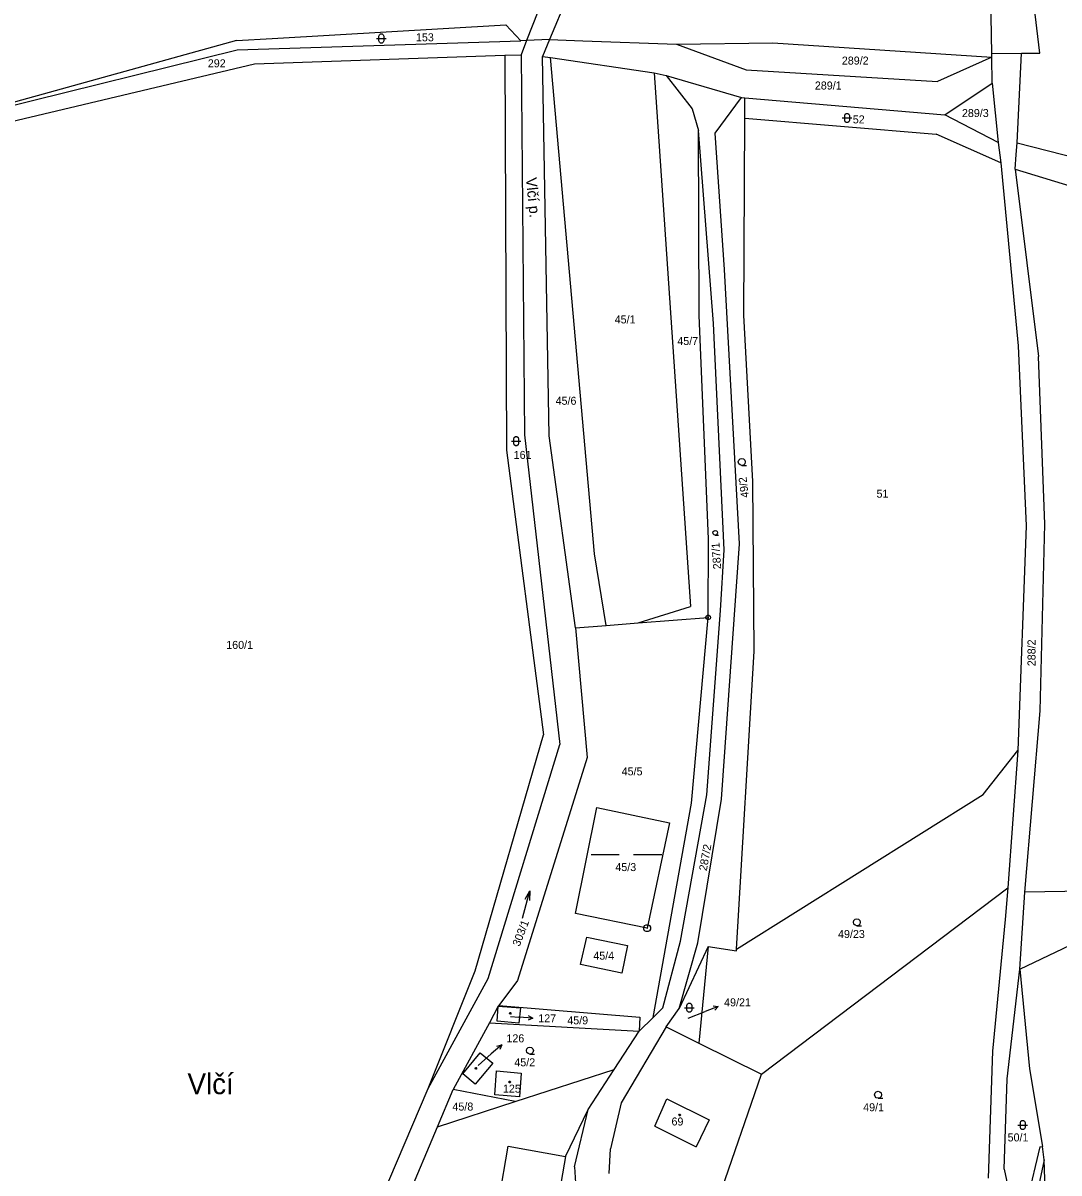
# Model space of a CAD drawing. Extents: x -780000 to -777378, y -1011169 to -1009297.
# Drawn here: x -779206.4 to -778986.4, y -1010124.6 to -1009880.5 of the extents above; entities that cross this region are included whole.
import ezdxf

# ---------------------------------------------------------------- set-up
doc = ezdxf.new("R2010")
doc.units = 0
for name, color, linetype in [('Default', 7, 'Continuous'), ('KN_HRANICE', 7, 'Continuous'), ('KN_KULTURY', 7, 'Continuous'), ('KN_PARCELY', 7, 'Continuous'), ('KN_SLUCKY', 7, 'Continuous')]:
    doc.layers.add(name, color=color, linetype=linetype)

# ---------------------------------------------------------------- blocks, each defined once
blk = doc.blocks.new('101')
at = {"layer": 'Default'}
blk.add_line((-0.05, 0), (0.05, 0), dxfattribs=at)
blk.add_lwpolyline([(0.19, 0.72), (0.53, 0.53), (0.72, 0.19), (0.72, -0.2), (0.53, -0.54), (0.19, -0.73), (-0.2, -0.73), (-0.54, -0.54), (-0.73, -0.2), (-0.73, 0.19), (-0.54, 0.53), (-0.2, 0.72), (0.19, 0.72)], dxfattribs=at)
blk = doc.blocks.new('304')
at = {"layer": 'Default'}
blk.add_lwpolyline([(0, 0), (-0.38, 0.1), (-0.65, 0.37), (-0.75, 0.74), (-0.65, 1.11), (-0.38, 1.38), (-0.01, 1.48), (0.36, 1.38), (0.63, 1.11), (0.73, 0.73), (0.63, 0.35), (0.36, 0.08), (-0.02, -0.02), (0.98, -0.02)], dxfattribs=at)
blk = doc.blocks.new('316')
at = {"layer": 'Default'}
for points in [[(-1, 1), (0.27, 1), (1, 1)], [(-0.5, 1.5), (-0.4, 1.79), (-0.15, 1.97), (0.16, 1.97), (0.41, 1.79), (0.51, 1.5), (0.51, 0.5), (0.41, 0.21), (0.16, 0.03), (-0.15, 0.03), (-0.4, 0.21), (-0.5, 0.5), (-0.5, 1.5)]]:
    blk.add_lwpolyline(points, dxfattribs=at)
blk = doc.blocks.new('802')
at = {"layer": 'Default'}
blk.add_line((-3, 0), (3, 0), dxfattribs=at)
blk.add_lwpolyline([(1, 0.5), (3, 0), (1, -0.5)], dxfattribs=at)
blk = doc.blocks.new('803')
at = {"layer": 'Default'}
for p, q in [((-7.5, 0), (-1.5, 0)), ((1.5, 0), (7.5, 0))]:
    blk.add_line(p, q, dxfattribs=at)
blk = doc.blocks.new('10292')
at = {"layer": 'Default'}
blk.add_line((0, 3), (0, 0), dxfattribs=at)
blk.add_lwpolyline([(-0.5, 2), (0, 3), (0.5, 2)], dxfattribs=at)
blk = doc.blocks.new('105')
at = {"layer": 'Default'}
blk.add_line((-0.12, 0), (0.12, 0), dxfattribs=at)
blk.add_lwpolyline([(0.15, 0.48), (0.4, 0.3), (0.5, 0.01), (0.4, -0.28), (0.15, -0.46), (-0.16, -0.46), (-0.41, -0.28), (-0.51, 0.01), (-0.41, 0.3), (-0.16, 0.48), (0.15, 0.48)], dxfattribs=at)
blk = doc.blocks.new('402')
at = {"layer": 'Default'}
blk.add_lwpolyline([(0.09, 0.15), (0.18, 0), (0.09, -0.15), (-0.09, -0.15), (-0.18, 0), (-0.09, 0.15), (0.09, 0.15)], dxfattribs=at)

msp = doc.modelspace()

# ---------------------------------------------------------------- linework, layer by layer
at = {"layer": 'KN_HRANICE'}
for p, q in [((-778990.51, -1009886.89), (-778995.32, -1009846.4)), ((-779090.96, -1009862.3), (-779099.45, -1009884.17)), ((-779085.09, -1009861.37), (-779094.6, -1009883.98)), ((-779000.69, -1009886.92), (-779001.1, -1009864.61)), ((-779153.46, -1009883.76), (-779103.85, -1009880.84)), ((-779100.65, -1009884.22), (-779103.85, -1009880.84)), ((-779161.05, -1009884.21), (-779228.01, -1009902.71)), ((-779161.05, -1009884.21), (-779153.46, -1009883.76)), ((-779160.94, -1009886.18), (-779100.65, -1009884.22)), ((-779099.45, -1009884.17), (-779100.65, -1009884.22)), ((-779099.45, -1009884.17), (-779100.62, -1009887.2)), ((-779094.6, -1009883.98), (-779099.45, -1009884.17)), ((-779094.6, -1009883.98), (-779096.11, -1009887.57)), ((-779094.6, -1009883.98), (-779087.51, -1009884.24)), ((-779087.51, -1009884.24), (-779067.61, -1009884.97)), ((-779228.01, -1009902.71), (-779160.94, -1009886.18)), ((-779067.61, -1009884.97), (-779047.2, -1009884.67)), ((-779067.61, -1009884.97), (-779052.83, -1009890.38)), ((-779047.2, -1009884.67), (-779000.66, -1009887.68)), ((-779000.69, -1009886.92), (-778994.39, -1009886.9)), ((-779000.66, -1009887.68), (-779000.69, -1009886.92)), ((-778995.28, -1009905.9), (-778994.39, -1009886.9)), ((-778994.39, -1009886.9), (-778990.51, -1009886.89)), ((-779229.16, -1009906.17), (-779157.23, -1009889.11)), ((-779157.23, -1009889.11), (-779104.09, -1009887.32)), ((-779104.09, -1009887.32), (-779100.62, -1009887.2)), ((-779104.09, -1009887.32), (-779103.74, -1009971.15)), ((-779100.62, -1009887.2), (-779099.92, -1009967.93)), ((-779096.11, -1009887.57), (-779094.38, -1009887.82)), ((-779094.66, -1009968.11), (-779096.11, -1009887.57)), ((-779085.07, -1009993.19), (-779094.38, -1009887.82)), ((-779094.38, -1009887.82), (-779072.34, -1009891.03)), ((-779000.66, -1009887.68), (-779012.19, -1009892.91)), ((-779000.59, -1009893.21), (-779000.66, -1009887.68)), ((-779072.34, -1009891.03), (-779064.62, -1010004.34)), ((-779072.34, -1009891.03), (-779069.8, -1009891.58)), ((-779069.8, -1009891.58), (-779064.32, -1009898.65)), ((-779069.8, -1009891.58), (-779053.8, -1009896.31)), ((-779052.83, -1009890.38), (-779012.19, -1009892.91)), ((-779010.63, -1009899.97), (-779000.59, -1009893.21)), ((-779000.59, -1009893.21), (-778999.33, -1009905.81)), ((-779059.45, -1009903.84), (-779053.8, -1009896.31)), ((-779053.8, -1009896.31), (-779053.14, -1009896.37)), ((-779053.15, -1009900.68), (-779053.14, -1009896.37)), ((-779053.14, -1009896.37), (-779010.63, -1009899.97)), ((-779064.32, -1009898.65), (-779062.96, -1009903.31)), ((-779053.3, -1009942.49), (-779053.15, -1009900.68)), ((-779053.15, -1009900.68), (-779012.48, -1009904.03)), ((-778999.33, -1009905.81), (-779010.63, -1009899.97)), ((-779059.75, -1009944.26), (-779062.96, -1009903.31)), ((-779062.79, -1009942.55), (-779062.96, -1009903.31)), ((-779057.44, -1009932.81), (-779059.45, -1009903.84)), ((-778998.76, -1009910.16), (-779012.48, -1009904.03)), ((-778999.33, -1009905.81), (-778998.76, -1009910.16)), ((-778995.48, -1009908.39), (-778995.28, -1009905.9)), ((-778995.28, -1009905.9), (-778982.29, -1009909.24)), ((-778995.73, -1009911.49), (-778995.48, -1009908.39)), ((-778998.76, -1009910.16), (-778995.06, -1009949.03)), ((-778995.73, -1009911.49), (-778990.76, -1009951.25)), ((-778995.73, -1009911.49), (-778981.54, -1009915.82)), ((-779054.27, -1009991.06), (-779057.44, -1009932.81)), ((-779060.86, -1009990.02), (-779062.79, -1009942.55)), ((-779051.39, -1009977.8), (-779053.3, -1009942.49)), ((-779057.48, -1009992.33), (-779059.75, -1009944.26)), ((-778995.06, -1009949.03), (-778993.39, -1009987.2)), ((-778989.44, -1009986.87), (-778990.76, -1009951.25)), ((-779099.92, -1009967.93), (-779092.42, -1010033.66)), ((-779089.05, -1010008.86), (-779094.66, -1009968.11)), ((-779103.74, -1009971.15), (-779095.87, -1010031.58)), ((-779051.15, -1010013.83), (-779051.39, -1009977.8)), ((-778990.39, -1010026.53), (-778989.44, -1009986.87)), ((-778993.39, -1009987.2), (-778995.17, -1010034.93)), ((-779060.91, -1010006.68), (-779060.86, -1009990.02)), ((-779058.05, -1010045.25), (-779054.27, -1009991.06)), ((-779082.54, -1010008.36), (-779085.07, -1009993.19)), ((-779058.32, -1010005.21), (-779057.48, -1009992.33)), ((-779075.8, -1010007.83), (-779064.62, -1010004.34)), ((-779061.16, -1010044.35), (-779058.32, -1010005.21)), ((-779089.05, -1010008.86), (-779082.54, -1010008.36)), ((-779089.05, -1010008.86), (-779086.6, -1010036.39)), ((-779082.54, -1010008.36), (-779075.8, -1010007.83)), ((-779075.8, -1010007.83), (-779060.91, -1010006.68)), ((-779064.44, -1010046.12), (-779060.91, -1010006.68)), ((-779054.9, -1010077.1), (-779051.15, -1010013.83)), ((-778993.67, -1010065.04), (-778990.39, -1010026.53)), ((-779110.38, -1010081.7), (-779095.87, -1010031.58)), ((-779107.64, -1010083.35), (-779092.42, -1010033.66)), ((-779002.52, -1010044.29), (-778995.17, -1010034.93)), ((-778995.17, -1010034.93), (-778997.31, -1010064.07)), ((-779086.6, -1010036.39), (-779101.39, -1010083.76)), ((-779066.77, -1010075.42), (-779061.16, -1010044.35)), ((-779063.12, -1010075.8), (-779058.05, -1010045.25)), ((-779054.9, -1010077.1), (-779002.52, -1010044.29)), ((-779089.06, -1010069.52), (-779084.56, -1010047.05)), ((-779084.56, -1010047.05), (-779069.14, -1010050.28)), ((-779072.56, -1010091.6), (-779064.44, -1010046.12)), ((-779069.14, -1010050.28), (-779073.83, -1010072.66)), ((-779049.6, -1010103.69), (-778997.31, -1010064.07)), ((-778997.31, -1010064.07), (-778997.81, -1010070.84)), ((-778994.71, -1010081.37), (-778993.67, -1010065.04)), ((-778974.33, -1010064.63), (-778993.67, -1010065.04)), ((-779073.83, -1010072.66), (-779089.06, -1010069.52)), ((-778997.81, -1010070.84), (-779000.52, -1010098.75)), ((-778994.71, -1010081.37), (-778973, -1010070.94)), ((-779088, -1010080.37), (-779086.7, -1010074.59)), ((-779086.7, -1010074.59), (-779078, -1010076.35)), ((-779078, -1010076.35), (-779079.25, -1010082.22)), ((-779070.51, -1010089.59), (-779066.77, -1010075.42)), ((-779067.03, -1010089.73), (-779063.12, -1010075.8)), ((-779060.9, -1010076.56), (-779067.03, -1010089.73)), ((-779060.9, -1010076.56), (-779062.88, -1010097.07)), ((-779060.9, -1010076.56), (-779054.92, -1010077.47)), ((-779054.92, -1010077.47), (-779054.9, -1010077.1)), ((-779120.37, -1010106.68), (-779110.38, -1010081.7)), ((-779079.25, -1010082.22), (-779088, -1010080.37)), ((-778997.43, -1010104.66), (-778994.71, -1010081.37)), ((-778994.71, -1010081.37), (-778992.7, -1010102.54)), ((-779120.37, -1010106.68), (-779107.64, -1010083.35)), ((-779101.39, -1010083.76), (-779105.37, -1010089.07)), ((-779105.46, -1010089.23), (-779107.32, -1010092.76)), ((-779105.69, -1010092.38), (-779105.46, -1010089.23)), ((-779105.37, -1010089.07), (-779105.46, -1010089.23)), ((-779105.46, -1010089.23), (-779100.74, -1010089.58)), ((-779105.37, -1010089.07), (-779075.41, -1010091.53)), ((-779100.74, -1010089.58), (-779101.1, -1010092.8)), ((-779072.56, -1010091.6), (-779070.51, -1010089.59)), ((-779075.41, -1010091.53), (-779075.53, -1010094.51)), ((-779075.53, -1010094.51), (-779072.56, -1010091.6)), ((-779069.85, -1010093.6), (-779067.03, -1010089.73)), ((-779107.32, -1010092.76), (-779115.05, -1010106.91)), ((-779107.32, -1010092.76), (-779075.53, -1010094.51)), ((-779101.1, -1010092.8), (-779105.69, -1010092.38)), ((-779080.84, -1010102.65), (-779075.53, -1010094.51)), ((-779069.85, -1010093.6), (-779079.37, -1010109.72)), ((-779069.85, -1010093.6), (-779062.88, -1010097.07)), ((-779113.02, -1010103.61), (-779109.32, -1010099.13)), ((-779109.32, -1010099.13), (-779106.65, -1010101.32)), ((-779062.88, -1010097.07), (-779049.6, -1010103.69)), ((-779000.52, -1010098.75), (-779001.45, -1010125.72)), ((-779106.65, -1010101.32), (-779110.37, -1010105.81)), ((-779110.37, -1010105.81), (-779113.02, -1010103.61)), ((-779106.22, -1010108.04), (-779105.84, -1010102.95)), ((-779105.84, -1010102.95), (-779100.59, -1010103.41)), ((-779101.88, -1010109.48), (-779080.84, -1010102.65)), ((-779100.59, -1010103.41), (-779100.93, -1010108.44)), ((-779086.41, -1010111.17), (-779080.84, -1010102.65)), ((-779059.16, -1010131.37), (-779049.6, -1010103.69)), ((-778992.7, -1010102.54), (-778989.92, -1010119.02)), ((-779134.25, -1010139.27), (-779120.37, -1010106.68)), ((-778998.08, -1010123.85), (-778997.43, -1010104.66)), ((-779118.39, -1010114.83), (-779115.05, -1010106.91)), ((-779101.88, -1010109.48), (-779115.05, -1010106.91)), ((-779100.93, -1010108.44), (-779106.22, -1010108.04)), ((-779118.39, -1010114.83), (-779101.88, -1010109.48)), ((-779091.18, -1010121.13), (-779086.41, -1010111.17)), ((-779089.32, -1010123.35), (-779086.41, -1010111.17)), ((-779079.37, -1010109.72), (-779081.62, -1010119.49)), ((-779127.92, -1010137.41), (-779118.39, -1010114.83)), ((-779091.18, -1010121.13), (-779096.36, -1010150.77)), ((-779081.9, -1010124.73), (-779081.62, -1010119.49)), ((-778990.45, -1010119.1), (-778994.99, -1010137.88)), ((-778990.45, -1010119.1), (-778989.92, -1010119.02)), ((-778989.56, -1010121.87), (-778989.92, -1010119.02)), ((-779089.32, -1010123.35), (-779087.92, -1010144.17)), ((-778989.56, -1010121.87), (-778993.95, -1010142.6)), ((-778988.54, -1010154.56), (-778989.56, -1010121.87)), ((-778998.08, -1010123.85), (-778994.99, -1010137.88))]:
    msp.add_line(p, q, dxfattribs=at)
at = {"layer": 'KN_PARCELY'}
for p, q in [((-779102.84, -1010091.44), (-779101.12, -1010091.56)), ((-779065.15, -1010091.78), (-779061.55, -1010090.36)), ((-779109.71, -1010101.8), (-779106.95, -1010099.37))]:
    msp.add_line(p, q, dxfattribs=at)
at = {"layer": 'KN_SLUCKY'}
for p, q in [((-779072.23, -1010114.72), (-779069.68, -1010108.87)), ((-779069.68, -1010108.87), (-779060.71, -1010113.33)), ((-779060.71, -1010113.33), (-779063.43, -1010119.08)), ((-779072.23, -1010114.72), (-779063.43, -1010119.08)), ((-779108.53, -1010148.76), (-779103.38, -1010118.93)), ((-779103.38, -1010118.93), (-779091.18, -1010121.13))]:
    msp.add_line(p, q, dxfattribs=at)

# ---------------------------------------------------------------- block references
at = {"layer": 'KN_KULTURY'}
for name, p in [('316', (-779130.3, -1009884.76)), ('316', (-779031.42, -1009901.63)), ('316', (-779101.67, -1009970.24)), ('304', (-779053.75, -1009974.4)), ('803', (-779078.27, -1010057.03)), ('304', (-779029.33, -1010072.14)), ('316', (-779064.9, -1010090.54)), ('402', (-779102.93, -1010090.73)), ('304', (-779098.74, -1010099.39)), ('402', (-779110.22, -1010102.41)), ('402', (-779103.07, -1010105.31)), ('304', (-779024.82, -1010108.76)), ('402', (-779066.93, -1010112.33)), ('316', (-778994.12, -1010115.45))]:
    msp.add_blockref(name, p, dxfattribs=at)
at = {"layer": 'KN_KULTURY', "xscale": 0.67, "yscale": 0.67}
msp.add_blockref('304', (-779059.4, -1009989.18), dxfattribs=at)
at = {"layer": 'KN_KULTURY', "rotation": 74.94288}
msp.add_blockref('802', (-779099.55, -1010067.62), dxfattribs=at)
at = {"layer": 'KN_PARCELY'}
for name, p in [('105', (-779060.91, -1010006.68)), ('101', (-779073.86, -1010072.65))]:
    msp.add_blockref(name, p, dxfattribs=at)
for p, rotation in [((-779061.55, -1010090.36), -68.364482), ((-779101.12, -1010091.56), -93.74651300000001), ((-779106.95, -1010099.37), -48.76932600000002)]:
    msp.add_blockref('10292', p, dxfattribs=dict(at, rotation=rotation))

# ---------------------------------------------------------------- texts
for s, height, p in [('153', 1.7, (-779122.95, -1009884.35)), ('292', 1.7, (-779167.14, -1009889.87)), ('289/2', 1.7, (-779032.52, -1009889.29)), ('289/1', 1.7, (-779038.25, -1009894.58)), ('289/3', 1.7, (-779007.02, -1009900.43)), ('52', 1.7, (-779030.2, -1009901.78)), ('45/1', 1.7, (-779080.75, -1009944.25)), ('45/7', 1.7, (-779067.46, -1009948.83)), ('45/6', 1.7, (-779093.3, -1009961.52)), ('161', 1.7, (-779102.2, -1009973.02)), ('51', 1.7, (-779025.16, -1009981.25)), ('160/1', 1.7, (-779163.23, -1010013.36)), ('45/5', 1.7, (-779079.27, -1010040.21)), ('45/3', 1.7, (-779080.61, -1010060.53)), ('49/23', 1.7, (-779033.33, -1010074.74)), ('45/4', 1.7, (-779085.29, -1010079.34)), ('49/21', 1.7, (-779057.52, -1010089.25)), ('127', 0.1, (-779102.82, -1010091.44)), ('127', 1.7, (-779096.98, -1010092.65)), ('45/9', 1.7, (-779090.82, -1010093.07)), ('49/21', 0.1, (-779065.14, -1010091.78)), ('126', 1.7, (-779103.74, -1010096.9)), ('126', 0.1, (-779109.69, -1010101.8)), ('45/2', 1.7, (-779102.06, -1010101.99)), ('Vlčí', 4.4, (-779171.45, -1010107.91)), ('125', 1.7, (-779104.48, -1010107.58)), ('45/8', 1.7, (-779115.2, -1010111.38)), ('49/1', 1.7, (-779027.99, -1010111.53)), ('69', 1.7, (-779068.69, -1010114.55)), ('50/1', 1.7, (-778997.32, -1010117.93))]:
    msp.add_text(s, height=height, dxfattribs=at).set_placement(p)
for s, height, rotation, p in [('Vlčí p.', 2.3, 275.936, (-779099.64, -1009913.4)), ('49/2', 1.7, 96.944, (-779052.24, -1009981.17)), ('287/1', 1.7, 93.908, (-779058.13, -1009996.39)), ('288/2', 1.7, 90.012, (-778991.4, -1010017.04)), ('287/2', 1.7, 79.87, (-779061.21, -1010060.59)), ('303/1', 1.7, 68.984, (-779100.95, -1010076.65))]:
    msp.add_text(s, height=height, rotation=rotation, dxfattribs=at).set_placement(p)

doc.saveas('drawing.dxf')
